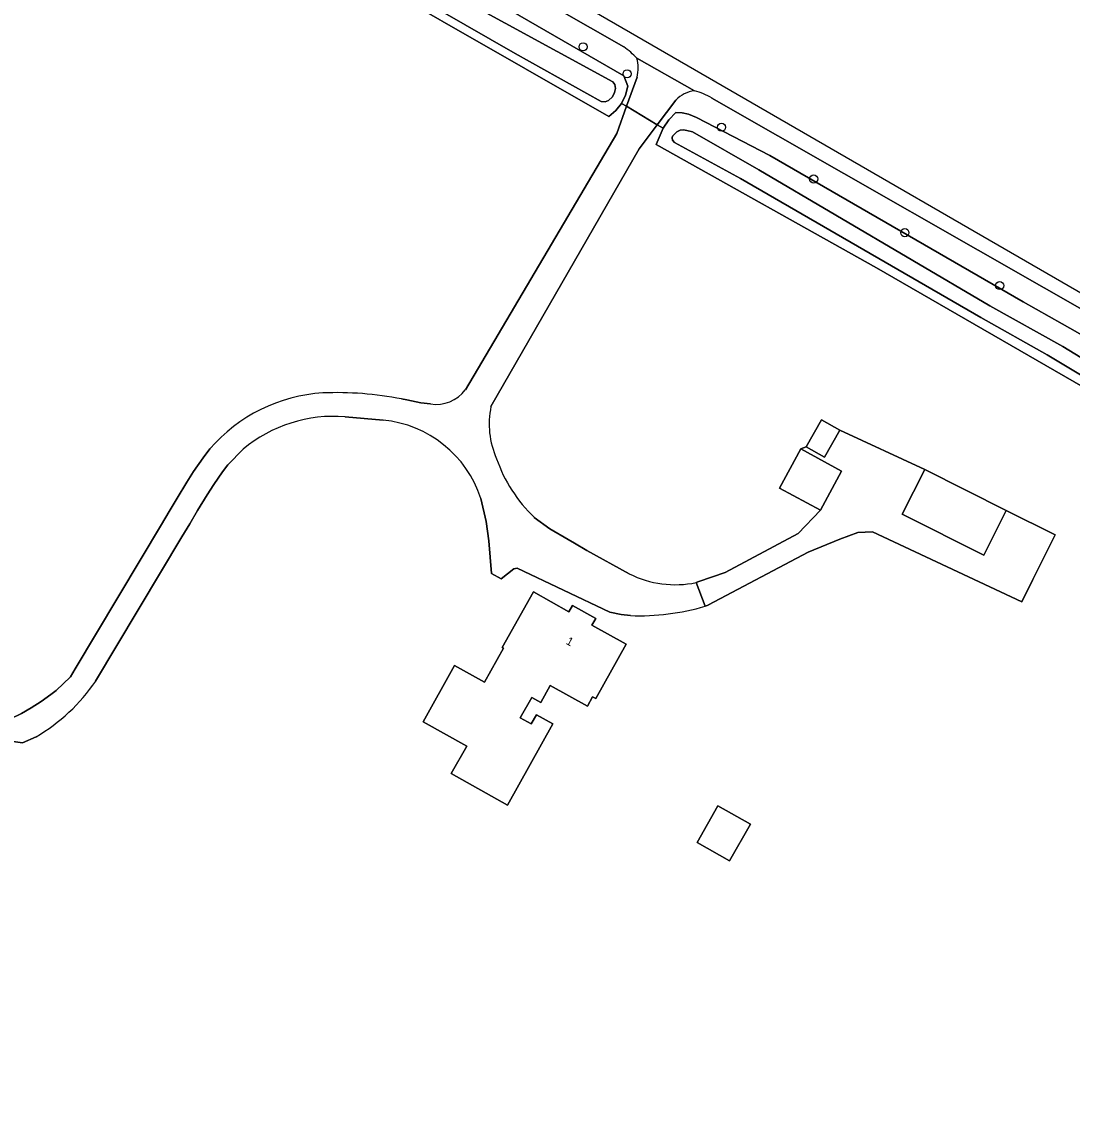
# Model space of a CAD drawing. Extents: x 156502 to 159075, y 384229 to 386100.
# Drawn here: x 158870.1 to 158996.6, y 384937.1 to 385068.6 of the extents above; entities that cross this region are included whole.
import ezdxf

# ---------------------------------------------------------------- set-up
doc = ezdxf.new("R2010")
doc.units = 0
for name, color, linetype in [('IMGEO_Boom', 7, 'Continuous'), ('IMGEO_Gemengd_bos', 7, 'Continuous'), ('IMGEO_Groenvoorziening', 7, 'Continuous'), ('IMGEO_Inrit_gesloten', 7, 'Continuous'), ('IMGEO_Oever', 7, 'Continuous'), ('IMGEO_Pand', 7, 'Continuous'), ('IMGEO_Pand_nummerreeks', 7, 'Continuous'), ('IMGEO_Rijbaan_lokaal_gesloten', 7, 'Continuous'), ('IMGEO_Waterloop', 7, 'Continuous')]:
    doc.layers.add(name, color=color, linetype=linetype)

msp = doc.modelspace()

# ---------------------------------------------------------------- linework, layer by layer
at = {"layer": 'IMGEO_Boom'}
for centre in [(158937.7, 385065.61), (158943, 385062.35), (158954.38, 385055.92), (158965.49, 385049.69), (158976.47, 385043.21), (158987.9, 385036.84)]:
    msp.add_circle(centre, 0.489, dxfattribs=at)
at = {"layer": 'IMGEO_Gemengd_bos'}
for points in [[(158923.51, 385024.29), (158941.77, 385055.15), (158942.94, 385058.44), (158942.32, 385058.77), (158941.64, 385057.92), (158940.81, 385057.23), (158859.86, 385103.52), (158774.28, 385152.08), (158662.11, 385216.13), (158603.48, 385250), (158587.52, 385259.81), (158556.68, 385251.65), (158555.42, 385250.01), (158519.21, 385188.85)], [(158877.84, 384756.47), (158893.69, 384779.91), (158952.98, 384867.63), (158983.01, 384912.57), (159000, 384934.86), (159030.55, 384976.89), (159042.89, 384997.7), (159042.95, 384998.18), (159042.56, 384998.73), (159029.69, 385006.3), (159000, 385023.43), (158973.04, 385038.98), (158946.52, 385053.84), (158947.34, 385055.8), (158946.64, 385056.22), (158944.46, 385053.32), (158926.59, 385022.28)], [(158915.82, 385023.18), (158916.45, 385023.07), (158918.14, 385022.73), (158919.31, 385022.59)], [(158913.61, 385020.61), (158909.01, 385021.04)], [(158951.33, 385001.06), (158951.66, 385001.18), (158954.8, 385002.27), (158963.63, 385006.95), (158966.31, 385009.79), (158961.38, 385012.45), (158963.93, 385017.16), (158964.58, 385017.42), (158966.42, 385020.68), (158968.65, 385019.42), (158978.86, 385014.67), (158988.7, 385009.75), (158994.58, 385006.81), (158991.89, 385001.41), (158990.55, 384998.75), (158972.56, 385007.19), (158970.8, 385007.08), (158968.65, 385006.29), (158964.81, 385004.73), (158952.83, 384998.37), (158952.76, 384998.34), (158952.41, 384998.21)], [(158896.74, 385017.12), (158894.9, 385015.25), (158894.23, 385014.4), (158893.19, 385012.88), (158892.41, 385011.64), (158891.25, 385009.74), (158890.3, 385008.15), (158889.36, 385006.57), (158878.96, 384989.18)], [(158887.82, 385009.63), (158888.78, 385011.23), (158889.95, 385013.16), (158890.77, 385014.46), (158891.9, 385016.1), (158892.72, 385017.16)], [(158943.4, 384997.08), (158942.27, 384997.21), (158940.91, 384997.5), (158929.75, 385002.79), (158929.36, 385002.73), (158927.84, 385001.49), (158926.65, 385002.15), (158926.33, 385006.1), (158926, 385008.42), (158925.36, 385011.19)], [(158871.78, 384982.48), (158870.15, 384981.73), (158864.12, 384982.6), (158863.65, 384982.67), (158867.35, 384984.08), (158868.68, 384984.62), (158870.02, 384985.27), (158871.19, 384985.95), (158872.38, 384986.74), (158873.55, 384987.59), (158874.19, 384988.07), (158875.93, 384989.68), (158876.48, 384990.67), (158886.88, 385008.05), (158887.82, 385009.63)], [(158931.82, 385008.91), (158933.7, 385007.54), (158935.89, 385006.25), (158936.68, 385005.79), (158938.16, 385004.92), (158943.26, 385002.12)]]:
    msp.add_lwpolyline(points, dxfattribs=at)
for points in [[(158922.22, 384991.08), (158925.82, 384989.06), (158928.11, 384993.16), (158927.96, 384993.24), (158931.72, 384999.95), (158936, 384997.55), (158936.42, 384998.31), (158939.22, 384996.74), (158938.76, 384995.93), (158942.89, 384993.62), (158939.22, 384987.07), (158938.83, 384987.29), (158938.21, 384986.17), (158933.75, 384988.67), (158932.59, 384986.61), (158931.51, 384987.21), (158930.13, 384984.75), (158931.44, 384984.02), (158932.07, 384985.14), (158934.06, 384984.02), (158928.58, 384974.25), (158921.82, 384978.04), (158923.68, 384981.34), (158918.42, 384984.29)], [(158953.95, 384974.16), (158957.86, 384971.94), (158955.35, 384967.51), (158951.43, 384969.72)]]:
    msp.add_lwpolyline(points, close=True, dxfattribs=at)
for centre, radius, start, end in [((158920.02, 385026.85), 4.32, 260.5126, 323.7758), ((158907.54, 385004.39), 19.56, 93.4931, 139.2461), ((158908.01, 384983.39), 40.55, 78.8958, 92.354), ((158936.67, 385020.18), 10.29, 168.1979, 204.0633), ((158907.71, 385003.94), 17.15, 85.6652, 129.7815), ((158912.33, 385006.99), 13.69, 17.8898, 84.6361), ((158944.09, 385021.81), 17.8, 199.1202, 226.442), ((158948.81, 385013.16), 12.36, 243.3157, 281.7529), ((158944.47, 385025.09), 28.03, 267.8223, 286.4497), ((158860.5, 385001.75), 22.33, 300.3479, 325.767)]:
    msp.add_arc(centre, radius, start, end, dxfattribs=at)
at = {"layer": 'IMGEO_Groenvoorziening'}
for points in [[(158942.61, 385065.61), (158854.77, 385115.68), (158831.21, 385129.16), (158829.41, 385126.26), (158913.09, 385079.19), (158942.62, 385062.12), (158943.1, 385060.85), (158942.82, 385059.77), (158942.32, 385058.77), (158942.94, 385058.44), (158944.2, 385061.97)], [(158948.88, 385059.19), (158946.64, 385056.22), (158947.34, 385055.8), (158948.02, 385056.81), (158948.87, 385057.68), (158949.63, 385057.66), (158950.42, 385057.5), (158951.36, 385057.1), (158960.21, 385052.52), (158990.71, 385034.88), (158995.43, 385032.25), (159017.37, 385019.83)], [(159056.02, 384982.17), (159056.33, 384982.59), (159061.03, 384979.4), (159060.76, 384978.97), (159062.54, 384981.57), (159065.3, 384985.73), (159061.33, 384988.46), (159055.57, 384992.42), (159059.88, 384998.7), (159058.37, 384999.6), (159050.75, 385003.85), (159049.23, 385004.63), (158953.23, 385059.44)]]:
    msp.add_lwpolyline(points, dxfattribs=at)
for centre, radius, start, end in [((158936.75, 385057.28), 10.18, 43.0435, 54.8774), ((158940.1, 385063.09), 4.25, 344.726, 15.6285), ((158951.51, 385056.73), 3.6, 96.2011, 137.0107), ((158948.75, 385051.59), 9.04, 60.2728, 74.8035)]:
    msp.add_arc(centre, radius, start, end, dxfattribs=at)
at = {"layer": 'IMGEO_Inrit_gesloten'}
for points in [[(158951.12, 385060.31), (158944.19, 385064.23)], [(158944.2, 385061.97), (158942.94, 385058.44), (158946.64, 385056.22), (158948.88, 385059.19)], [(158946.64, 385056.22), (158942.94, 385058.44), (158941.77, 385055.15), (158923.51, 385024.29)], [(158926.59, 385022.28), (158944.46, 385053.32), (158946.64, 385056.22)], [(158919.31, 385022.59), (158918.14, 385022.73), (158916.45, 385023.07), (158915.82, 385023.18)], [(158909.01, 385021.04), (158913.61, 385020.61)], [(158892.72, 385017.16), (158891.9, 385016.1), (158890.77, 385014.46), (158889.95, 385013.16), (158888.78, 385011.23), (158887.82, 385009.63), (158886.88, 385008.05), (158876.48, 384990.67), (158875.93, 384989.68), (158874.19, 384988.07), (158873.55, 384987.59), (158872.38, 384986.74), (158871.19, 384985.95), (158870.02, 384985.27), (158868.68, 384984.62), (158867.35, 384984.08), (158863.65, 384982.67), (158864.12, 384982.6), (158870.15, 384981.73), (158871.78, 384982.48)], [(158878.96, 384989.18), (158889.36, 385006.57), (158890.3, 385008.15), (158891.25, 385009.74), (158892.41, 385011.64), (158893.19, 385012.88), (158894.23, 385014.4), (158894.9, 385015.25), (158896.74, 385017.12)], [(158925.36, 385011.19), (158926, 385008.42), (158926.33, 385006.1), (158926.65, 385002.15), (158927.84, 385001.49), (158929.36, 385002.73), (158929.75, 385002.79), (158940.91, 384997.5), (158942.27, 384997.21), (158943.4, 384997.08)], [(158943.26, 385002.12), (158938.16, 385004.92), (158936.68, 385005.79), (158935.89, 385006.25), (158933.7, 385007.54), (158931.82, 385008.91)], [(158952.41, 384998.21), (158951.33, 385001.06)]]:
    msp.add_lwpolyline(points, dxfattribs=at)
for centre, radius, start, end in [((158940.1, 385063.09), 4.25, 344.726, 15.6285), ((158951.51, 385056.73), 3.6, 96.2011, 137.0107), ((158920.02, 385026.85), 4.32, 260.5126, 323.7758), ((158907.54, 385004.39), 19.56, 93.4931, 139.2461), ((158908.01, 384983.39), 40.55, 78.8958, 92.354), ((158936.67, 385020.18), 10.29, 168.1979, 204.0633), ((158907.71, 385003.94), 17.15, 85.6652, 129.7815), ((158912.33, 385006.99), 13.69, 17.8898, 84.6361), ((158944.09, 385021.81), 17.8, 199.1202, 226.442), ((158948.81, 385013.16), 12.36, 243.3157, 281.7529), ((158944.47, 385025.09), 28.03, 267.8223, 286.4497), ((158860.5, 385001.75), 22.33, 300.3479, 325.767)]:
    msp.add_arc(centre, radius, start, end, dxfattribs=at)
at = {"layer": 'IMGEO_Oever'}
for points in [[(158587.52, 385259.81), (158603.48, 385250), (158662.11, 385216.13), (158774.28, 385152.08), (158859.86, 385103.52), (158940.81, 385057.23), (158941.64, 385057.92), (158942.32, 385058.77), (158942.82, 385059.77), (158943.1, 385060.85), (158942.62, 385062.12), (158913.09, 385079.19), (158829.41, 385126.26)], [(158908.63, 385079.24), (158941.3, 385061.41), (158941.53, 385061.08), (158941.6, 385060.57), (158941.5, 385060.1), (158941.25, 385059.57), (158940.77, 385059.15), (158940.34, 385059), (158939.86, 385059.04), (158929.52, 385064.8), (158881.59, 385092.31)], [(159017.37, 385019.83), (158995.43, 385032.25), (158990.71, 385034.88), (158960.21, 385052.52), (158951.36, 385057.1), (158950.42, 385057.5), (158949.63, 385057.66), (158948.87, 385057.68), (158948.02, 385056.81), (158947.34, 385055.8), (158946.52, 385053.84), (158973.04, 385038.98), (159000, 385023.43)], [(159005.69, 385021.28), (158993.61, 385028.49), (158985.61, 385032.98), (158956.65, 385049.75), (158948.71, 385054.1), (158948.48, 385054.37), (158948.43, 385054.65), (158948.48, 385054.85), (158948.63, 385055.01), (158948.98, 385055.36), (158949.4, 385055.55), (158949.8, 385055.61), (158950.18, 385055.52), (158950.87, 385055.35), (158958.87, 385050.8), (158986.7, 385034.41), (158995.51, 385029.52), (159016.57, 385016.65)]]:
    msp.add_lwpolyline(points, dxfattribs=at)
at = {"layer": 'IMGEO_Pand'}
for points in [[(158966.42, 385020.68), (158964.58, 385017.42), (158966.8, 385016.16), (158968.65, 385019.42)], [(158963.93, 385017.16), (158961.38, 385012.45), (158966.31, 385009.79), (158968.85, 385014.5)], [(158988.7, 385009.75), (158978.86, 385014.67), (158976.16, 385009.28), (158986, 385004.36)], [(158928.58, 384974.25), (158934.06, 384984.02), (158932.07, 384985.14), (158931.44, 384984.02), (158930.13, 384984.75), (158931.51, 384987.21), (158932.59, 384986.61), (158933.75, 384988.67), (158938.21, 384986.17), (158938.83, 384987.29), (158939.22, 384987.07), (158942.89, 384993.62), (158938.76, 384995.93), (158939.22, 384996.74), (158936.42, 384998.31), (158936, 384997.55), (158931.72, 384999.95), (158927.96, 384993.24), (158928.11, 384993.16), (158925.82, 384989.06), (158922.22, 384991.08), (158918.42, 384984.29), (158923.68, 384981.34), (158921.82, 384978.04)], [(158955.35, 384967.51), (158957.86, 384971.94), (158953.95, 384974.16), (158951.43, 384969.72)]]:
    msp.add_lwpolyline(points, close=True, dxfattribs=at)
at = {"layer": 'IMGEO_Rijbaan_lokaal_gesloten'}
for points in [[(159060.52, 384999.64), (158723.57, 385194.36), (158517.19, 385311.58), (158092.75, 385552.64)], [(158097.27, 385549.05), (158217.58, 385480.1), (158547.45, 385291.41), (158557.32, 385285.41), (158559.02, 385284.79), (158582.28, 385271.49), (158593.54, 385264.82), (158594.64, 385264.37), (158831.21, 385129.16), (158854.77, 385115.68), (158942.61, 385065.61)], [(158944.19, 385064.23), (158951.12, 385060.31)], [(158953.23, 385059.44), (159049.23, 385004.63), (159050.75, 385003.85), (159058.37, 384999.6), (159059.88, 384998.7), (159060.52, 384999.64)]]:
    msp.add_lwpolyline(points, dxfattribs=at)
msp.add_lwpolyline([(158976.16, 385009.28), (158978.86, 385014.67), (158968.65, 385019.42), (158966.8, 385016.16), (158964.58, 385017.42), (158963.93, 385017.16), (158968.85, 385014.5), (158966.31, 385009.79), (158963.63, 385006.95), (158954.8, 385002.27), (158951.66, 385001.18), (158951.33, 385001.06), (158952.41, 384998.21), (158952.76, 384998.34), (158952.83, 384998.37), (158964.81, 385004.73), (158968.65, 385006.29), (158970.8, 385007.08), (158972.56, 385007.19), (158990.55, 384998.75), (158991.89, 385001.41), (158994.58, 385006.81), (158988.7, 385009.75), (158986, 385004.36)], close=True, dxfattribs=at)
for centre, radius, start, end in [((158936.75, 385057.28), 10.18, 43.0435, 54.8774), ((158948.75, 385051.59), 9.04, 60.2728, 74.8035)]:
    msp.add_arc(centre, radius, start, end, dxfattribs=at)
at = {"layer": 'IMGEO_Waterloop'}
for points in [[(158881.59, 385092.31), (158929.52, 385064.8), (158939.86, 385059.04), (158940.34, 385059), (158940.77, 385059.15), (158941.25, 385059.57), (158941.5, 385060.1), (158941.6, 385060.57), (158941.53, 385061.08), (158941.3, 385061.41), (158908.63, 385079.24)], [(159016.57, 385016.65), (158995.51, 385029.52), (158986.7, 385034.41), (158958.87, 385050.8), (158950.87, 385055.35), (158950.18, 385055.52), (158949.8, 385055.61), (158949.4, 385055.55), (158948.98, 385055.36), (158948.63, 385055.01), (158948.48, 385054.85), (158948.43, 385054.65), (158948.48, 385054.37), (158948.71, 385054.1), (158956.65, 385049.75), (158985.61, 385032.98), (158993.61, 385028.49), (159005.69, 385021.28)]]:
    msp.add_lwpolyline(points, dxfattribs=at)

# ---------------------------------------------------------------- texts
at = {"layer": 'IMGEO_Pand_nummerreeks'}
msp.add_text('1', height=1, rotation=332.2785, dxfattribs=at).set_placement((158935.55, 384993.7))

doc.saveas('drawing.dxf')
